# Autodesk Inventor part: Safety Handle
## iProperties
Shininess: 77.0
Length Units: 11269
Angle Units: 11279
Time Units: 11290
Mass Units: 11283
Length Display Precision: 3
Angle Display Precision: 2
Created: 2002-02
Part Number: Safety Handle
Document SubType Name: Modeling
Designer: ***
Density: 0.0
Volumn: 0.0
Area: 0.0
PropertySet Name: Model Information
Control State: 0
Master: False
Checked Out: False
Author: ***
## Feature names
1. Revolution1
2. Extrusion1
